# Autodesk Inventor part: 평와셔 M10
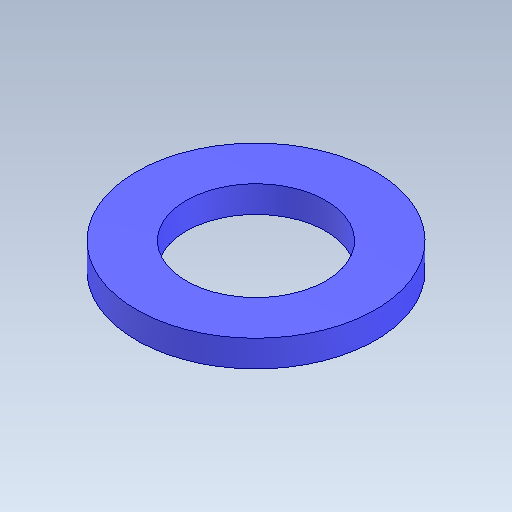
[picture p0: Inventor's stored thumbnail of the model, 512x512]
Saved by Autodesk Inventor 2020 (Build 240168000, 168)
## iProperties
Created: 2024-04
Part Number: 평와셔 M10
Material: 강철, 연강
Document SubType Name: Modeling
Designer: oem
Density: 7.86 g/cm^3
Appearance: 기본값
Mass: 2.63906 g
Surface Area: 5.14828 cm^2
Volume: 0.335758 cm^3
Sending System: Autodesk Inventor 2025
Preprocessor: ST-DEVELOPER v20
Author: jhkim
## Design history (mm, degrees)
feature "솔리드1"
node "솔리드2"
